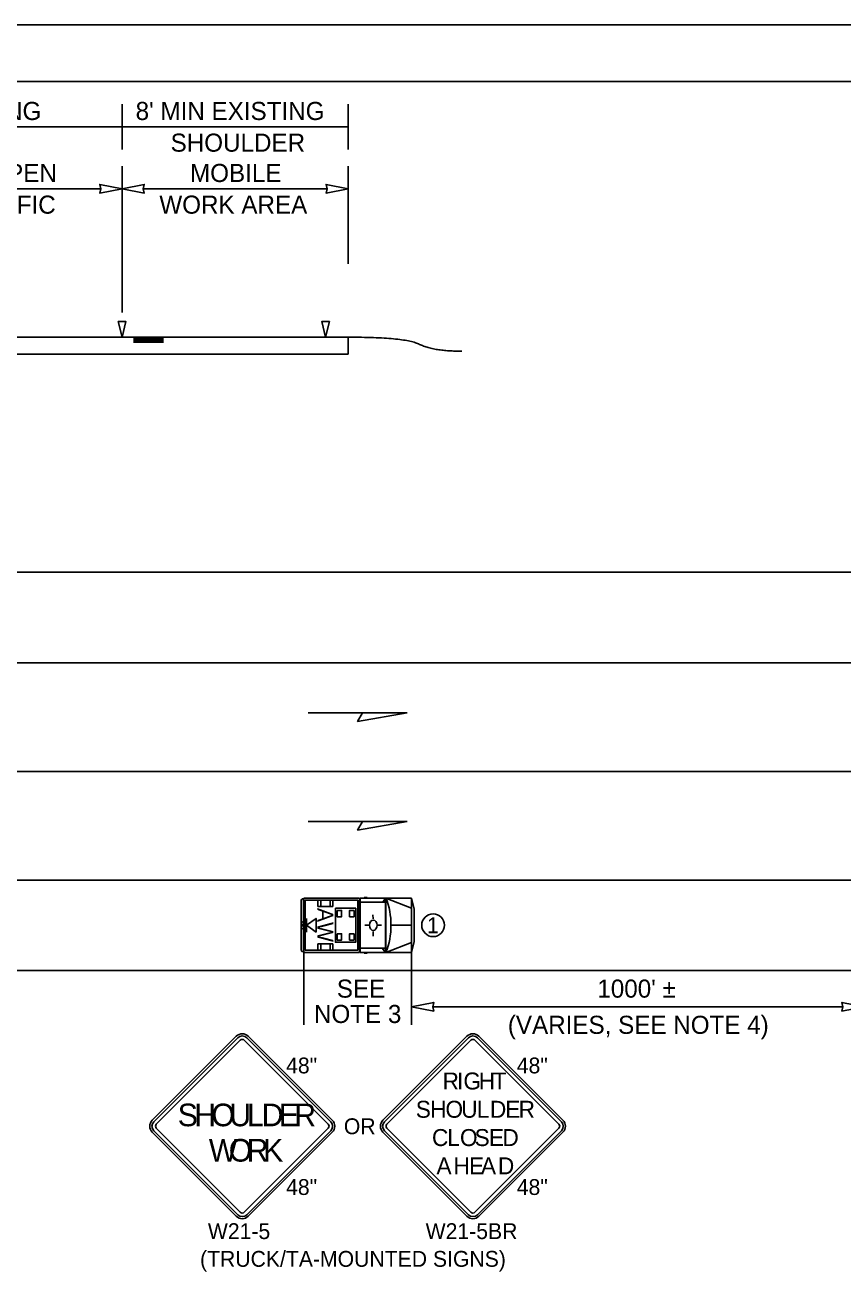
# Model space of a CAD drawing. Extents: x 0 to 17, y 0 to 11.
# Drawn here: x 8.43 to 12.04, y 5.47 to 11 of the extents above; entities that cross this region are included whole.
import ezdxf

# ---------------------------------------------------------------- set-up
doc = ezdxf.new("R2010")
doc.units = 0
for name, color, linetype in [('RD_ED_ShoulderPavedEdge', 7, 'Continuous'), ('RD_MK_LineEdgeWhite', 7, 'Continuous'), ('RD_MK_LineEdgeYellow', 7, 'Continuous'), ('RD_MK_LineLane', 7, 'Continuous'), ('SH_GI_PlotLimits', 7, 'Continuous'), ('SH_GI_SheetBorder3', 7, 'Continuous'), ('SH_TI_WZSectionCut', 7, 'Continuous'), ('TR_SN_ConstructionSigns', 7, 'Continuous'), ('TR_WZ_PortableSignMountBlk-Org', 7, 'Continuous'), ('TR_WZ_ProtectiveVehicle', 7, 'Continuous'), ('TR_WZ_TransportableAttenuator', 7, 'Continuous'), ('TR_WZ_WorkZoneDetails', 7, 'Continuous'), ('TR_WZ_WorkZoneTextCurrent', 7, 'Continuous')]:
    doc.layers.add(name, color=color, linetype=linetype)

msp = doc.modelspace()

# ---------------------------------------------------------------- linework, layer by layer
at = {"layer": 'RD_ED_ShoulderPavedEdge'}
for p, q in [((1.8283, 8.5807), (16.62, 8.5807)), ((1.8283, 6.8207), (16.62, 6.8207))]:
    msp.add_line(p, q, dxfattribs=at)
at = {"layer": 'RD_MK_LineEdgeWhite'}
msp.add_line((1.8283, 7.2207), (16.62, 7.2207), dxfattribs=at)
at = {"layer": 'RD_MK_LineEdgeYellow'}
msp.add_line((1.8283, 8.1807), (16.62, 8.1807), dxfattribs=at)
at = {"layer": 'RD_MK_LineLane'}
msp.add_line((16.62, 7.7007), (1.8283, 7.7007), dxfattribs=at)
at = {"layer": 'SH_GI_PlotLimits'}
msp.add_lwpolyline([(0, 11), (17, 11), (17, 0), (0, 0)], close=True, dxfattribs=at)
at = {"layer": 'SH_GI_SheetBorder3'}
msp.add_line((1, 10.75), (16.75, 10.75), dxfattribs=at)
at = {"layer": 'SH_TI_WZSectionCut'}
for p, q in [((8.8546, 10.45), (8.8546, 10.65)), ((9.8546, 10.45), (9.8546, 10.65)), ((7.6546, 10.55), (8.8546, 10.55)), ((8.8546, 10.55), (9.8546, 10.55)), ((8.8546, 9.7297), (8.8546, 10.376)), ((9.8546, 9.9449), (9.8546, 10.376)), ((8.7609, 10.276), (7.7484, 10.276)), ((9.7609, 10.276), (8.9484, 10.276)), ((9.8546, 9.6199), (5.4546, 9.6199)), ((9.0376, 9.6143), (8.9046, 9.6143)), ((9.8546, 9.6199), (9.8546, 9.5449)), ((9.0376, 9.6087), (8.9046, 9.6087)), ((9.0376, 9.603), (8.9046, 9.603)), ((9.0376, 9.5978), (8.9046, 9.5978)), ((9.8546, 9.5449), (5.4546, 9.5449))]:
    msp.add_line(p, q, dxfattribs=at)
for points in [[(8.8546, 10.276), (8.7564, 10.2567), (8.7609, 10.276), (8.7564, 10.2953)], [(8.8546, 10.276), (8.9529, 10.2567), (8.9484, 10.276), (8.9529, 10.2953)], [(9.8546, 10.276), (9.7564, 10.2567), (9.7609, 10.276), (9.7564, 10.2953)], [(8.838, 9.6897), (8.8713, 9.6897), (8.8547, 9.6199)]]:
    msp.add_lwpolyline(points, close=True, dxfattribs=at)
msp.add_lwpolyline([(9.7713, 9.6897), (9.7379, 9.6897), (9.7546, 9.6199), (9.7713, 9.6897)], dxfattribs=at)
msp.add_open_spline([(9.8546, 9.6199), (10.1058, 9.6201), (10.2313, 9.558), (10.3568, 9.5581)], degree=2, dxfattribs=at)
at = {"layer": 'TR_SN_ConstructionSigns'}
for p, q in [((9.3597, 6.5301), (8.9884, 6.1588)), ((9.3663, 6.5234), (8.9951, 6.1522)), ((9.7773, 6.1522), (9.4061, 6.5234)), ((9.784, 6.1588), (9.4127, 6.5301)), ((10.3791, 6.5301), (10.0079, 6.1588)), ((10.3858, 6.5234), (10.0145, 6.1522)), ((10.7968, 6.1522), (10.4255, 6.5234)), ((10.8034, 6.1588), (10.4322, 6.5301)), ((9.0061, 6.1411), (9.3774, 6.5124)), ((9.395, 6.5124), (9.7663, 6.1411)), ((10.0256, 6.1411), (10.3968, 6.5124)), ((10.4145, 6.5124), (10.7857, 6.1411)), ((8.9884, 6.1058), (9.3597, 5.7345)), ((8.9951, 6.1124), (9.3663, 5.7412)), ((9.3774, 5.7522), (9.0061, 6.1235)), ((9.7663, 6.1235), (9.395, 5.7522)), ((9.4061, 5.7412), (9.7773, 6.1124)), ((9.4127, 5.7345), (9.784, 6.1058)), ((10.0079, 6.1058), (10.3791, 5.7345)), ((10.0145, 6.1124), (10.3858, 5.7412)), ((10.3968, 5.7522), (10.0256, 6.1235)), ((10.7857, 6.1235), (10.4145, 5.7522)), ((10.4255, 5.7412), (10.7968, 6.1124)), ((10.4322, 5.7345), (10.8034, 6.1058))]:
    msp.add_line(p, q, dxfattribs=at)
for centre, radius, start, end in [((9.3862, 6.5036), 0.0375, 45, 135), ((9.3862, 6.5036), 0.0281, 45, 135), ((10.4057, 6.5036), 0.0375, 45, 135), ((10.4057, 6.5036), 0.0281, 45, 135), ((9.3862, 6.5036), 0.0125, 45, 135), ((10.4057, 6.5036), 0.0125, 45, 135), ((9.015, 6.1323), 0.0375, 135, 225), ((9.015, 6.1323), 0.0281, 135, 225), ((9.015, 6.1323), 0.0125, 135, 225), ((9.7575, 6.1323), 0.0125, 315, 45), ((9.7575, 6.1323), 0.0281, 315, 45), ((9.7575, 6.1323), 0.0375, 315, 45), ((10.0344, 6.1323), 0.0375, 135, 225), ((10.0344, 6.1323), 0.0281, 135, 225), ((10.0344, 6.1323), 0.0125, 135, 225), ((10.7769, 6.1323), 0.0125, 315, 45), ((10.7769, 6.1323), 0.0281, 315, 45), ((10.7769, 6.1323), 0.0375, 315, 45), ((9.3862, 5.7611), 0.0125, 225, 315), ((10.4057, 5.7611), 0.0125, 225, 315), ((9.3862, 5.7611), 0.0375, 225, 315), ((9.3862, 5.7611), 0.0281, 225, 315), ((10.4057, 5.7611), 0.0375, 225, 315), ((10.4057, 5.7611), 0.0281, 225, 315)]:
    msp.add_arc(centre, radius, start, end, dxfattribs=at)
at = {"layer": 'TR_WZ_PortableSignMountBlk-Org'}
msp.add_line((9.6696, 6.9907), (9.6696, 7.0507), dxfattribs=at)
msp.add_lwpolyline([(9.6696, 7.0207), (9.7127, 7.0507), (9.7127, 6.9907)], close=True, dxfattribs=at)
at = {"layer": 'TR_WZ_ProtectiveVehicle'}
for p, q in [((9.6462, 6.912), (9.6462, 7.1295)), ((9.6515, 7.1368), (9.6569, 7.1368)), ((9.6569, 6.9047), (9.6569, 7.1368)), ((9.6577, 7.1407), (9.9046, 7.1407)), ((9.6577, 6.9007), (9.6577, 7.1407)), ((9.6647, 6.9103), (9.6647, 7.1312)), ((9.6647, 7.1312), (9.8976, 7.1312)), ((9.7204, 7.1312), (9.7204, 7.1035)), ((9.7335, 7.1312), (9.7335, 7.1035)), ((9.7743, 7.1312), (9.7743, 7.1035)), ((9.7863, 7.1312), (9.7863, 7.1035)), ((9.8976, 6.9103), (9.8976, 7.1312)), ((9.9046, 6.9007), (9.9046, 7.1407)), ((9.9079, 6.9007), (9.9079, 7.1407)), ((10.1346, 7.1407), (9.9079, 7.1407)), ((9.9388, 7.1441), (9.9252, 7.1441)), ((10.0072, 7.1221), (10.0192, 7.1407)), ((10.0192, 6.9007), (10.0192, 7.1407)), ((10.0212, 6.9007), (10.0212, 7.1407)), ((10.1346, 7.0968), (10.0212, 7.1407)), ((10.1346, 6.9007), (10.1346, 7.1407)), ((10.1346, 7.1407), (10.1457, 7.0923)), ((9.7204, 7.1035), (9.7863, 7.1035)), ((10.0192, 7.1221), (9.9079, 7.1221)), ((10.1457, 6.9492), (10.1457, 7.0923)), ((9.6462, 7.0376), (9.6569, 7.0331)), ((9.6491, 7.0207), (9.654, 7.0207)), ((9.6515, 7.0173), (9.6515, 7.0241)), ((9.9277, 7.0216), (9.9456, 7.0212)), ((9.9479, 7.0211), (9.9479, 7.0211)), ((9.9639, 7.0669), (9.9642, 7.0488)), ((10.0009, 7.0206), (9.9858, 7.0206)), ((10.1346, 7.0207), (10.0435, 7.0207)), ((9.6462, 7.0038), (9.6569, 7.0083)), ((9.9648, 6.9732), (9.9648, 6.9925)), ((9.6647, 6.9103), (9.8976, 6.9103)), ((9.7204, 6.9379), (9.7863, 6.9379)), ((9.7204, 6.9103), (9.7204, 6.9379)), ((9.7335, 6.9103), (9.7335, 6.9379)), ((9.7743, 6.9103), (9.7743, 6.9379)), ((9.7863, 6.9103), (9.7863, 6.9379)), ((10.0192, 6.9193), (9.9079, 6.9193)), ((10.0192, 6.9007), (10.0047, 6.9193)), ((10.1346, 6.9447), (10.0212, 6.9007)), ((10.1346, 6.9007), (10.1457, 6.9492)), ((9.6515, 6.9047), (9.6569, 6.9047)), ((9.6577, 6.9007), (9.9046, 6.9007)), ((10.1346, 6.9007), (9.9079, 6.9007)), ((9.9388, 6.8973), (9.9252, 6.8973))]:
    msp.add_line(p, q, dxfattribs=at)
for centre, major_axis, start_param, end_param in [((9.6515, 7.1295), (0, 0.00732), 0, 1.570796), ((9.8592, 7.0208), (0, 0.2518), 4.215667, 5.208926), ((9.6515, 6.912), (0, -0.00732), 4.712389, 6.283185)]:
    msp.add_ellipse(centre, major_axis=major_axis, ratio=0.73155, start_param=start_param, end_param=end_param, dxfattribs=at)
for centre, major_axis in [((9.6515, 7.0207), (0, -0.00338)), ((9.9648, 7.0207), (0, -0.0231))]:
    msp.add_ellipse(centre, major_axis=major_axis, ratio=0.73155, dxfattribs=at)
at = {"layer": 'TR_WZ_TransportableAttenuator'}
for points in [[(9.7976, 7.0957), (9.8876, 7.0957), (9.8876, 6.9457), (9.7976, 6.9457)], [(9.8051, 7.0864), (9.8251, 7.0864), (9.8251, 7.0582), (9.8051, 7.0582)], [(9.8801, 7.0864), (9.8601, 7.0864), (9.8601, 7.0582), (9.8801, 7.0582)], [(9.8051, 6.9832), (9.8251, 6.9832), (9.8251, 6.9551), (9.8051, 6.9551)], [(9.8801, 6.9832), (9.8601, 6.9832), (9.8601, 6.9551), (9.8801, 6.9551)]]:
    msp.add_lwpolyline(points, close=True, dxfattribs=at)
at = {"layer": 'TR_WZ_WorkZoneDetails'}
for p, q in [((9.9182, 7.96), (9.6771, 7.96)), ((9.9182, 7.48), (9.6771, 7.48)), ((9.6577, 6.9007), (9.6577, 6.5811)), ((10.1346, 6.9007), (10.1346, 6.5807)), ((12.0408, 6.6607), (10.2283, 6.6607))]:
    msp.add_line(p, q, dxfattribs=at)
for points in [[(10.1147, 7.96), (9.8959, 7.9214), (9.9182, 7.96)], [(10.1147, 7.48), (9.8959, 7.4414), (9.9182, 7.48)], [(10.1346, 6.6607), (10.2328, 6.68), (10.2283, 6.6607), (10.2328, 6.6415)], [(12.1346, 6.6607), (12.0363, 6.68), (12.0408, 6.6607), (12.0363, 6.6415)]]:
    msp.add_lwpolyline(points, close=True, dxfattribs=at)
msp.add_circle((10.2294, 7.0207), 0.05, dxfattribs=at)

# ---------------------------------------------------------------- texts
at = {"layer": 'SH_TI_WZSectionCut'}
for s, p in [('EXISTING', (7.9986, 10.58)), ("8' MIN EXISTING", (8.9148, 10.58)), ('SHOULDER', (9.0693, 10.44))]:
    msp.add_text(s, height=0.08, rotation=360, dxfattribs=at).set_placement(p)
for s, p in [('LANE OPEN', (7.9543, 10.306)), ('MOBILE', (9.1551, 10.306)), ('TO TRAFFIC', (7.9315, 10.166)), ('WORK AREA', (9.0196, 10.166))]:
    msp.add_text(s, height=0.08, dxfattribs=at).set_placement(p)
at = {"layer": 'TR_SN_ConstructionSigns'}
for s, height, p in [('48"', 0.07, (9.5798, 6.366)), ('48"', 0.07, (10.5993, 6.366)), ('R', 0.075, (10.2714, 6.2948)), ('I', 0.075, (10.3351, 6.2948)), ('G', 0.075, (10.3636, 6.2948)), ('H', 0.075, (10.4312, 6.2948)), ('T', 0.075, (10.4934, 6.2948)), ('S', 0.075, (10.1529, 6.1698)), ('H', 0.075, (10.2166, 6.1698)), ('O', 0.075, (10.2841, 6.1698)), ('U', 0.075, (10.3539, 6.1698)), ('L', 0.075, (10.4229, 6.1698)), ('D', 0.075, (10.4807, 6.1698)), ('E', 0.075, (10.5482, 6.1698)), ('R', 0.075, (10.6074, 6.1698)), ('S', 0.1, (9.1007, 6.1323)), ('H', 0.1, (9.1737, 6.1323)), ('O', 0.1, (9.2497, 6.1323)), ('U', 0.1, (9.3287, 6.1323)), ('L', 0.1, (9.4067, 6.1323)), ('D', 0.1, (9.4717, 6.1323)), ('E', 0.1, (9.5477, 6.1323)), ('R', 0.1, (9.6157, 6.1323)), ('C', 0.075, (10.2245, 6.0448)), ('L', 0.075, (10.292, 6.0448)), ('O', 0.075, (10.3483, 6.0448)), ('S', 0.075, (10.4128, 6.0448)), ('E', 0.075, (10.4765, 6.0448)), ('D', 0.075, (10.5358, 6.0448)), ('W', 0.1, (9.2382, 5.976)), ('O', 0.1, (9.3262, 5.976)), ('R', 0.1, (9.4052, 5.976)), ('K', 0.1, (9.4782, 5.976)), ('A', 0.075, (10.2444, 5.9198)), ('H', 0.075, (10.3194, 5.9198)), ('E', 0.075, (10.3884, 5.9198)), ('A', 0.075, (10.4409, 5.9198)), ('D', 0.075, (10.5159, 5.9198)), ('48"', 0.07, (9.5798, 5.8286)), ('48"', 0.07, (10.5993, 5.8286)), ('W21-5', 0.07, (9.234, 5.6336)), ('W21-5BR', 0.07, (10.1966, 5.6336)), ('(TRUCK/TA-MOUNTED SIGNS)', 0.07, (9.1993, 5.5111))]:
    msp.add_text(s, height=height, dxfattribs=at).set_placement(p)
at = {"layer": 'TR_WZ_ProtectiveVehicle'}
msp.add_text('AW', height=0.07, rotation=270, dxfattribs=at).set_placement((9.7183, 7.0974))
at = {"layer": 'TR_WZ_WorkZoneDetails'}
for s, p in [('1', (10.2027, 6.9857)), ('OR', (9.835, 6.0973))]:
    msp.add_text(s, height=0.07, dxfattribs=at).set_placement(p)
at = {"layer": 'TR_WZ_WorkZoneTextCurrent'}
for s, p in [('SEE', (9.8039, 6.7007)), ("1000' ±", (10.9555, 6.7007)), ('NOTE 3', (9.7029, 6.5887)), ('(VARIES, SEE NOTE 4)', (10.5599, 6.5407))]:
    msp.add_text(s, height=0.08, dxfattribs=at).set_placement(p)

doc.saveas('drawing.dxf')
